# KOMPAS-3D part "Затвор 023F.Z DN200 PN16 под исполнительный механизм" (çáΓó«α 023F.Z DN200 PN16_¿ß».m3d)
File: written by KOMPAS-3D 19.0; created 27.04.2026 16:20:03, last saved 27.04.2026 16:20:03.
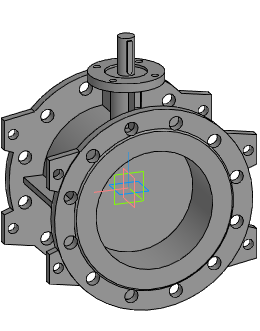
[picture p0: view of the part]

Document properties: Автор: Евгений; Полное имя файла: Z:\3.Личные\kachalov\3d для проектировщиков\1.7 Тип 023F.Z Затвор дисковый поворотный фланцевый с двумя эксцентриками\Затвор 023F.Z DN200-DN1600_исп\_stp_Затвор 023F.Z DN200-DN1600_исп\Затвор 023F.Z DN200 PN16_исп.m3d

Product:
- Part/product: Затвор 023F.Z DN200 PN16 под исполнительный механизм

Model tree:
1. Операция без истории:1  (labels: Затвор 023F.Z DN200 PN16 под исполнительный механизм)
